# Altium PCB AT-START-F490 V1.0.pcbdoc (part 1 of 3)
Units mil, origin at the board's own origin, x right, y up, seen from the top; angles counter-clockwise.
Board outline 15424.54 x 3536.36 mil, 2 copper layers (Top Layer, Bottom Layer); 130 components, 126 nets, 528 pads, 715 vias.
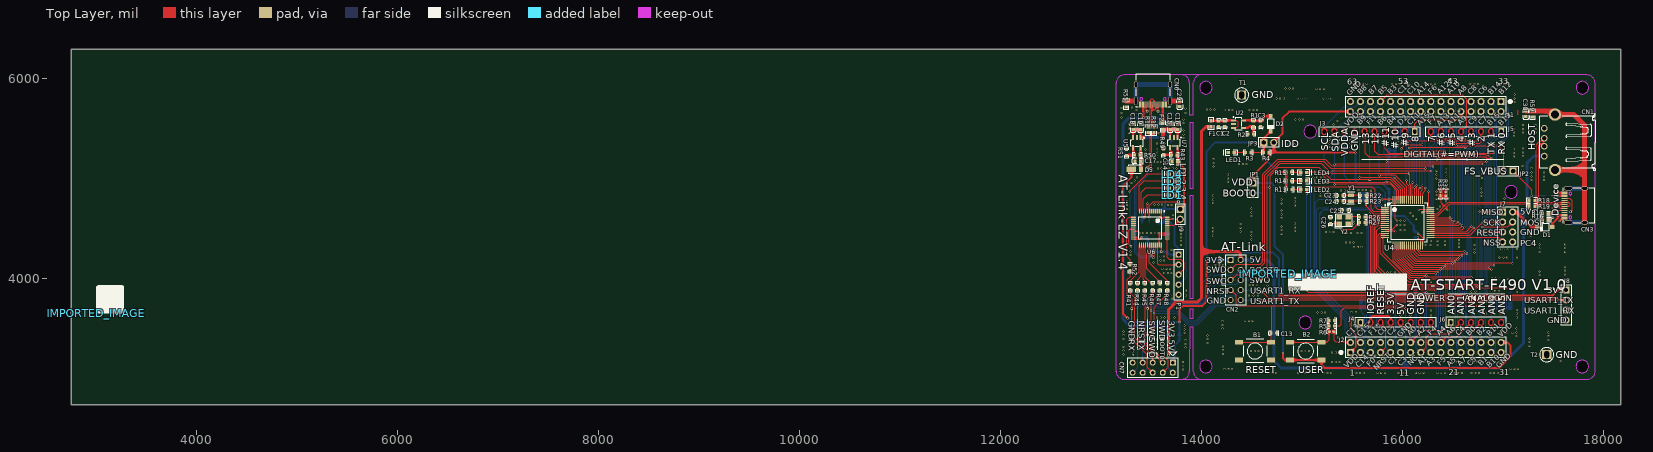
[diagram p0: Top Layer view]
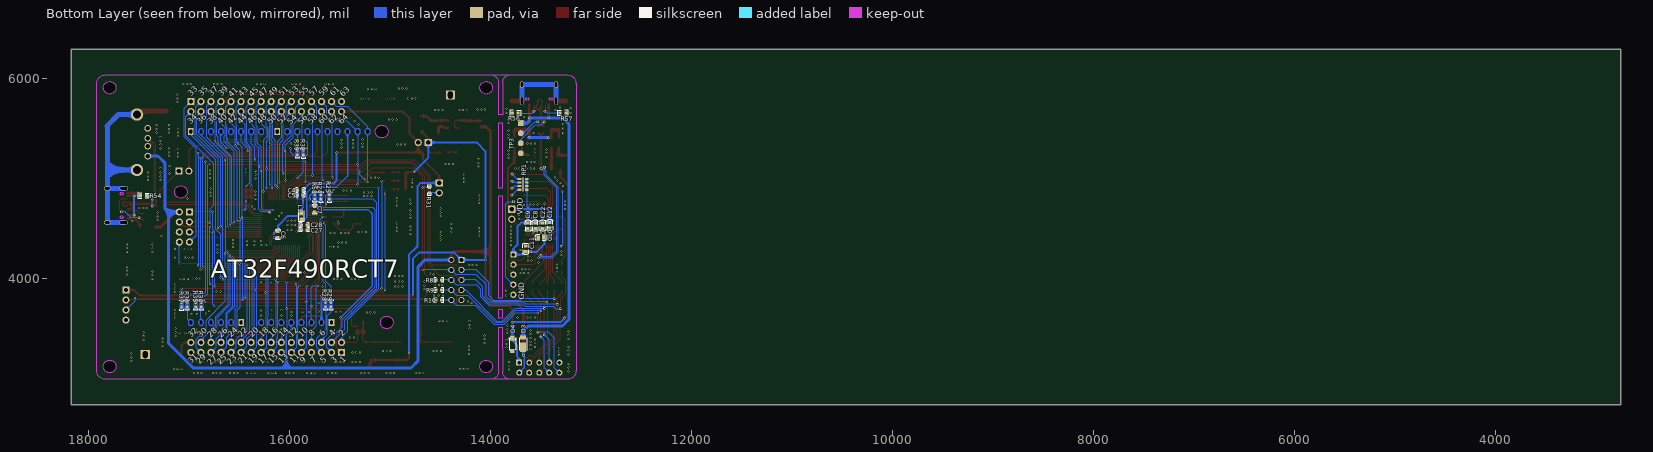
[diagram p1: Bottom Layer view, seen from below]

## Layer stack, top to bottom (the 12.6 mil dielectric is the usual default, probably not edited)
Top Layer: signal copper (thickness not stored)
Dielectric: dielectric 12.6, FR-4, Dk 4.8
Bottom Layer: signal copper (thickness not stored)

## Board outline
18174.54,2750 2750,2750 2750,6286.36 18174.54,6286.36
cut-out: 17855.2,5903.56 ccw(c17792.2,5903.57) 17729.21,5903.57 ccw(c17792.2,5903.57)
cut-out: 17854.57,3128.57 ccw(c17791.57,3128.57) 17728.58,3128.57 ccw(c17791.57,3128.57)
cut-out: 14107.57,3128.57 ccw(c14044.57,3128.57) 13981.58,3128.57 ccw(c14044.57,3128.57)
cut-out: 14107.57,5903.56 ccw(c14044.57,5903.57) 13981.58,5903.57 ccw(c14044.57,5903.57)
cut-out: 17146.57,4866.56 ccw(c17083.57,4866.57) 17020.58,4866.57 ccw(c17083.57,4866.57)
cut-out: 15096.57,3566.57 ccw(c15033.57,3566.57) 14970.58,3566.57 ccw(c15033.57,3566.57)
cut-out: 15146.57,5466.56 ccw(c15083.57,5466.57) 15020.58,5466.57 ccw(c15083.57,5466.57)

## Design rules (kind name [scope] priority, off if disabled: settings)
BoardOutlineClearance Default [All] p0: genericclearance=10 ignorepadtopadclearanceinfootprint=FALSE except(0: Arc-SplitContinuation Track-SplitContinuation SMDPad-SplitContinuation THPad-SplitContinuation Via-SplitContinuation Fill-SplitContinuation Poly-SplitContinuation Region-SplitContinuation Text-SplitContinuation; 6: Track-CutoutEdge SMDPad-CutoutEdge THPad-CutoutEdge Via-CutoutEdge Fill-CutoutEdge Region-CutoutEdge; 11.8: Track-OutlineEdge SMDPad-OutlineEdge THPad-OutlineEdge Via-OutlineEdge Fill-OutlineEdge Region-OutlineEdge Poly-OutlineEdge Text-OutlineEdge)
Clearance Default [(InNet('GND') OR InNet('3V3') OR InNet('ATLK_RX') OR InNet('PA0') OR InNet('VDD') OR InNet('NRST') OR InNet('PC2') OR InNet('PB9') OR InNet('PB3') OR InNet('PA13/SWDIO') OR InNet('PA14/SWCLK') OR InNet('PC5') OR InNet('PC3') OR InNet('PB8') OR InNet('PA10') OR InNet('PA9') OR InNet('PA2') OR InNet('PA3') OR InNet('PA7') OR InNet('PA6') OR InNet('PA5') OR InNet('PF1/HEXT_OUT') OR InNet('PC0') OR InNet('PC1') OR InNet('5V') OR InNet('SWO') OR InNet('LD4') OR InNet('VCC') OR InNet('M-NRST') OR InNet('M-USB_D+') OR InNet('M-USB_D-') OR InNet('USB-') OR InNet('USB+') OR InNet('ATLK_TX') OR InNet('ATLINK_5V') OR InNet('PB10') OR InNet('PB2') OR InNet('PB1') OR InNet('PB0') OR InNet('PC4') OR InNet('PA4') OR InNet('PF5') OR InNet('PF4') OR InNet('PA1') OR InNet('PC6') OR InNet('PB12') OR InNet('PC7') OR InNet('PC8') OR InNet('PC9') OR InNet('PA8') OR InNet('PF6') OR InNet('PF7') OR InNet('PA12') OR InNet('PA11') OR InNet('PA15') OR InNet('PC10') OR InNet('PC11') OR InNet('PC12') OR InNet('PD2') OR InNet('PB4') OR InNet('PB7') OR InNet('PB5') OR InNet('PB6') OR InNet('PF0/HEXT_IN') OR InNet('PC14/LEXT_IN') OR InNet('PC15/LEXT_OUT') OR InNet('PC13') OR InNet('VDDA') OR InNet('PB13') OR InNet('PA11_E') OR InNet('PA12_E') OR InNet('PF0') OR InNet('PC14') OR InNet('PF1') OR InNet('PC15') OR InNet('VCC3.5V') OR InNet('M_ATLK_NRST') OR InNet('M-ATLK_RX') OR InNet('M-ATLK_TX') OR InNet('M_ATLK_BOOT0') OR InNet('LD1') OR InNet('M-SWCLK') OR InNet('LD2') OR InNet('LD3') OR InNet('M_ATLK_SWO') OR InNet('M_ATLK_SWDIO') OR InNet('M_ATLK_SWCLK') OR InNet('M-SWDIO') OR InNet('$1N361') OR InNet('$1N307') OR InNet('$1N334') OR InNet('$1N335') OR InNet('$1N336') OR InNet('$1N337') OR InNet('$1N396') OR InNet('$1N467') OR InNet('$4N239') OR InNet('$4N238') OR InNet('$4N335') OR InNet('$4N333') OR InNet('BOOT0/PF11') OR InNet('$4N462') OR InNet('VBUS_FS') OR InNet('$2N290') OR InNet('$2N326') OR InNet('$2N490') OR InNet('$2N489') OR InNet('$2N337') OR InNet('$2N291') OR InNet('$2N488') OR InNet('$2N360') OR InNet('EGND') OR InNet('FD-') OR InNet('FD+') OR InNet('CC2') OR InNet('CC1') OR InNet('EGND2') OR InNet('FCC2') OR InNet('FCC1') OR InNet('$2N12490') OR InNet('$3N200') OR InNet('$3N199') OR InNet('$3N264') OR InNet('PB15') OR InNet('PB14') OR InNet('PB11'))] p1: gap=7 ignorepadtopadclearanceinfootprint=FALSE except(5: SMDPad-SMDPad SMDPad-THPad THPad-THPad SMDPad-Hole THPad-Hole; 6: Track-Track Track-SMDPad Track-THPad Track-Via SMDPad-Via THPad-Via Via-Via Track-Fill SMDPad-Fill THPad-Fill Via-Fill Fill-Fill Track-Region SMDPad-Region THPad-Region Via-Region Fill-Region Region-Region Track-Poly SMDPad-Poly THPad-Poly Via-Poly Fill-Poly Region-Poly Poly-Poly Track-Text SMDPad-Text THPad-Text Via-Text Fill-Text Region-Text Poly-Text Text-Text Track-Hole Via-Hole Fill-Hole Region-Hole Poly-Hole Text-Hole; 11.8: Track-Sheet SMDPad-Sheet THPad-Sheet Via-Sheet Fill-Sheet Region-Sheet Poly-Sheet Text-Sheet Sheet-Hole)
DiffPairsRouting differentialPair [All] p1: maxuncoupledlength=10 minlimit=6 maxlimit=6 mostfreqgap=6 toplayer_minwidth=6 toplayer_prefwidth=11.1 toplayer_maxwidth=100 bottomlayer_minwidth=6 bottomlayer_prefwidth=11.1 bottomlayer_maxwidth=100
PasteMaskExpansion pasteMaskExpansion [All] p1: expansion=0
PlaneConnect Default [All] p1: planeconnectstyle=Relief reliefexpansion=20 reliefentries=4 reliefconductorwidth=0 reliefairgap=10
PolygonConnect gge24930 [All] p1: connectstyle=Relief reliefentries=4 reliefconductorwidth=10 polygonreliefangle="90 Angle" airgapwidth=10
PolygonConnect gge24930(1) [All] p1: connectstyle=Relief reliefentries=4 reliefconductorwidth=10 polygonreliefangle="90 Angle" airgapwidth=10
RoutingVias Default [All] p1: viastyle="Through Hole" holewidth=12 minholewidth=7.9 maxholewidth=236.2 width=19.7 minwidth=19.7 maxwidth=393.7
SolderMaskExpansion solderMaskExpansion [All] p1: useseparateexpansions=TRUE expansion=2 expansionbottom=2
Width Default [All] p1: maxlimit=1000 minlimit=6 preferedwidth=6

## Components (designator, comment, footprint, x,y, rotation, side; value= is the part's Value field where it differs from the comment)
B1 "BUTTON_SMT,6.0x6.0x4.5mm" BUTTON_SMT_6*6*5 14533.58,3281.57 r0 top
B2 "BUTTON_SMT,6.0x6.0x4.5mm" BUTTON_SMT_6*6*5 15038.58,3281.57 r180 top
C1 "10uF" 0603_C-M 14172.58,5545.37 r90 top
C2 "0.1uF" 0603_C-M 14232.58,5545.37 r90 top
C3 "10uF" 0603_C-M 14590.58,5545.37 r90 top
C4 "4.7uF" 0603_C-M 15896.58,4884.56 r180 bottom
C5 "0.1uF" 0603_C-M 15897.08,4834.56 r180 bottom
C6 "0.1uF" 0603_C-M 16115.6,4442.33 r90 bottom
C7 "0.1uF" 0603_C-M 15750.58,4694.56 r90 bottom
C8 "4.7uF" C0603 13556.58,4528.56 r270 bottom
C9 "CC0603KRX7R9BB104" C0603 13628.58,4528.56 r270 bottom
C10 "CC0603KRX7R9BB104" C0603 13498.58,4412.56 r0 bottom
C11 "CC0603KRX7R9BB104" C0603 13650.58,4300.56 r90 bottom
C12 "CC0603KRX7R9BB104" C0603 13410.58,4534.56 r270 bottom
C13 "0.1uF" 0603_C-M 14720.58,3460.57 r0 top
C14 "CL10A106KP8NNNC" C0603 13736.58,5165.56 r180 top
C15 "CL10A106KP8NNNC" C0603 13689.58,5515.56 r90 top
C16 "CC0603KRX7R9BB104" C0603 13764.58,5515.12 r90 top
C17 "CL10A106KP8NNNC" C0603 13367.58,5173.56 r180 top
C18 "CL10A106KP8NNNC" C0603 13319.58,5514.56 r90 top
C19 "CC0603KRX7R9BB104" C0603 13395.58,5514.12 r90 top
C22 "CC0603KRX7R9BB104" C0603 13480.58,4530.56 r270 bottom
C23 "18pF" 0603_C-M 15383.58,4832.56 r180 top
C24 "18pF" 0603_C-M 15383.58,4773.56 r180 top
C25 "15pF" 0603_C-M 15433.08,4684.56 r180 top
C26 "15pF" 0603_C-M 15283.58,4577.06 r90 top
C27 "1uF" 0603_C-M 15857.08,4488.56 r180 bottom
C28 "0.1uF" 0603_C-M 15857.08,4537.56 r180 bottom
C29 "CC0603KRX7R9BB104" C0603 13784.58,5743.56 r90 top
C30 "CC0603KRX7R9BB104" C0603 17229.58,5643.01 r90 top
CN1 "USB type A" USB-A-TH__USB-AF-90 17466.58,5360.56 r90 top
CN2 "NC(Header 2x5)" HDR2X5#1 14290.92,4189.85 r270 top
CN3 "TYPEC-304-BCP16" USB-C-SMD_TYPEC-304-BCP16#1 17715.58,4731.56 r90 top
CN6 "TYPEC-304-BCP16" USB-C-SMD_TYPEC-304-BCP16#2 13518.58,5835.56 r180 top locked
CN7 "CON1" HDR2X5#2 13715.38,3166.97 r180 top
D1 "DFLS130L-7" SOD-123 17417.58,4515.56 r0 top
D2 "DFLS130L-7" SOD-123 14690.58,5545.36 r90 top
D3 "DFLS130L-7" POWERDI-123_L2.8-W1.8-LS3.7-RD 13676.62,3368.57 r90 bottom
D4 "SMF3.3A" SOD-123_L2.8-W1.8-LS3.7-RD 13782.58,3348.57 r270 bottom
D5 "DFLS130L-7" POWERDI-123_L2.8-W1.8-LS3.7-RD 13350.58,5091.56 r0 top
F1 "SMD0603B050TF" R0603#1 14096.58,5514.86 r90 top
F2 "SMD0603B050TF" R0603#2 13616.58,5518.56 r270 top
IMPORTED_IMAGE "IMPORTED_IMAGE" IMPORTED_IMAGE 3000,3659.57 r0 top
IMPORTED_IMAGE "IMPORTED_IMAGE" IMPORTED_IMAGE 14864.58,4052.57 r0 top
J1 "Header 2x16" HDR-M-2.54_2X16 16233.44,5715.86 r180 top
J2 "Header 2x16" HDR-M-2.54_2X16 16233.88,3318.14 r0 top
J3 "CON10" "FEMALE HEADER 1X10" 16123.87,5466.56 r180 top locked
J4 "CON8" "FEMALE HEADER 1X8" 15583.87,3566.56 r0 top locked
J5 "CON8" "FEMALE HEADER 1X8" 16983.87,5466.56 r180 top locked
J6 "CON6" "FEMALE HEADER 1X6" 16483.87,3566.57 r0 top locked
J7 "Header 4X2" HDR2X4 16998.88,4667.16 r270 top locked
J8 "Header 1x4" HDR1X4 17630.74,3890.57 r270 top locked
J9 "1X2P,Male,DIP_2.54" HDR1X2 13789.38,4693.97 r270 top
JP1 "NC(Header 1x2)" "HEADER 1X2" 14511.58,4956.56 r270 top
JP2 "NC(Header 1x2)" "HEADER 1X2" 17103.58,5073.56 r180 top
JP3 "NC(Header 1x2)" "HEADER 1X2" 14620.58,5358.56 r0 top
L1 "0.5A,600R@100Mhz" 0603_L 15884.58,4623.56 r270 bottom
LD1 "RED" LED0603 13742.58,4833.77 r180 top
LD2 "GREEN" LED0603 13742.58,4903.37 r180 top
LD3 "BLUE" LED0603 13742.58,4972.97 r180 top
LD4 "YELLOW" LED0603 13742.58,5042.56 r180 top
LED1 "RED" LED0603 14328.58,5259.56 r180 top
LED2 "RED" LED0603 14988.58,4890.56 r0 top
LED3 "YELLOW" LED0603 14988.58,4976.56 r0 top
LED4 "GREEN" LED0603 14988.58,5060.56 r0 top
P1 "HDR-M-2.54_1x5" HDR-M-2.54_1X5 13772.58,4042.57 r270 top
R1 "51k" 0603_R-M 14518.58,5545.37 r270 top
R2 "15k" 0603_R-M 14490.58,5444.56 r180 top
R3 "1K" 0603_R-M 14466.58,5259.56 r0 top
R4 "0R" 0603_R-M 14647.58,5258.56 r0 top
R5 "0R" 0603_R-M 15296.58,3530.57 r0 top
R6 "NC" SB-PAD 15296.58,3474.57 r0 top
R7 "100K" 0603_R-M 15296.58,3586.57 r180 top
R8 "470R" 0603_R-M 14518.27,3990.76 r0 bottom
R9 "470R" 0603_R-M 14518.27,3888.76 r0 bottom
R10 "470R" 0603_R-M 14518.27,3790.76 r0 bottom
R11 "0603WAF0000T5E" R0603#2 13469.58,5485.9 r270 top
R12 "0603WAF0000T5E" R0603#2 13528.58,5485.56 r270 top
R13 "1K" 0603_R-M 14872.58,4890.56 r0 top
R14 "1K" 0603_R-M 14871.19,4976.21 r0 top
R15 "1K" 0603_R-M 14871.19,5062.21 r0 top
R16 "0603WAF5101T5E" R0603#2 17423.58,4589.56 r180 top
R17 "0603WAF5101T5E" R0603#2 17422.58,4649.56 r180 top
R18 "0603WAF220JT5E" R0603#2 17291.92,4780.56 r0 top
R19 "0603WAF220JT5E" R0603#2 17291.58,4721.56 r0 top
R22 "0R" 0603_R-M 15609.58,4832.56 r0 top
R23 "0R" 0603_R-M 15611.58,4774.56 r0 top
R24 "NC" SB-PAD 15689.58,4815.56 r270 bottom
R25 "NC" SB-PAD 15605.58,4815.56 r270 bottom
R26 "0R" 0603_R-M 15600.58,4616.56 r0 top
R27 "0R" 0603_R-M 15600.58,4562.56 r0 top
R28 "NC" SB-PAD 15643.58,3742.57 r270 bottom
R29 "NC" SB-PAD 15589.58,3743.57 r270 bottom
R31 "10K" 0603_R-M 14610.58,4883.56 r270 bottom
R32 "NC" SB-PAD 16433.58,4848.44 r270 top
R33 "NC" SB-PAD 16380.58,4848.85 r270 top
R34 "0R" SB-PAD 16880.58,3742.45 r270 bottom
R35 "NC" SB-PAD 16936.58,3741.96 r270 bottom
R36 "NC" SB-PAD 17020.58,3741.45 r270 bottom
R37 "0R" SB-PAD 17076.58,3740.84 r270 bottom
R38 "NC" SB-PAD 15864.58,5253.93 r270 bottom
R39 "0R" SB-PAD 15924.58,5254.56 r270 bottom
R41 "33R" 0603_R-M 13290.58,3920.57 r270 top
R43 "47K" 0603_R-M 13730.42,5236.02 r180 top
R44 "33R" 0603_R-M 13364.58,3920.57 r270 top
R45 "33R" 0603_R-M 13436.58,3920.57 r270 top
R46 "33R" 0603_R-M 13514.58,3922.57 r270 top
R47 "33R" 0603_R-M 13586.58,3924.57 r270 top
R48 "33R" 0603_R-M 13660.58,3920.57 r270 top
R49 "15K" 0603_R-M 13620.58,5264.56 r270 top
R50 "51K" 0603_R-M 13362.58,5233.56 r180 top
R51 "15K" 0603_R-M 13254.58,5258.56 r270 top
R52 "33R" 0603_R-M 13288.58,4110.56 r270 top
R54 "0603WAF1002T5E" R0603#2 17455.92,4827.56 r0 bottom
R55 "RC0603FR-071ML" R0603#2 13250.58,5741.9 r270 top
R56 "0603WAF5101T5E" R0603#2 13755.58,5651.56 r0 bottom
R57 "0603WAF5101T5E" R0603#2 13279.58,5651.56 r180 bottom
R58 "0R" SB-PAD 15750.58,4817.56 r270 bottom
R59 "RC0603FR-071ML" R0603#2 17296.58,5641.9 r270 top
RP1 "1K" 0603*4,8P4R 13640.58,4887.56 r90 bottom
T1 "Testpoint" TESTHOOK 14400.58,5830.56 r270 top
T2 "Testpoint" TESTHOOK 17437.58,3246.57 r90 top
TP3 "1X4P_2.54F" "HDR1X4 - TOP" 13699.93,5551.02 r90 bottom
U2 "RT9080N-08GJ5" SOT-23-5 14382.58,5477.54 r0 top
U4 "AT32F490RxT7" lqfp-64_l10.0-w10.0-p0.50-ls12.0-bl 16053.57,4560.71 r270 top locked
U5 "RT9080N-08GJ5" SOT-23-5 13295.14,5340.91 r270 top
U6 "AT32F403CGT6" "LQFP48 - 2" 13600.09,4673.02 r270 top locked
U7 "RT9080N-08GJ5" SOT-23-5 13664.35,5342.91 r270 top
Y1 "32.768KHz" "XTAL_SOP - FC-12M" 15487.58,4832.56 r270 top
Y2 "CJ13-120001210B20" CRYSTAL-SMD_4P-L3.2-W2.5-BL 15416.58,4583.56 r0 top

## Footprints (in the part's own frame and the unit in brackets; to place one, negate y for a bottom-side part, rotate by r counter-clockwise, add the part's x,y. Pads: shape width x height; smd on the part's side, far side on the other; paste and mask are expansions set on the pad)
0603*4,8P4R [mm]
  rect 0.55x0.95 smd: 1(0,0) 4(2.7,0) 5(2.7,1.85) 8(0,1.85)
  rect 0.5x0.95 smd: 2(0.9,0) 3(1.8,0) 6(1.8,1.85) 7(0.9,1.85)
  silkscreen extent -0.43,0.94 3.1,0.94
0603_C-M [mil]
  rect 30x30 smd: 1(27.5,0) 2(-27.5,0)
  silkscreen extent -50,-21 50,21
0603_L [mm]
  rect 0.93x0.9 smd: 1(-0.77,0) 2(0.77,0)
  silkscreen extent -1.4,-0.64 1.4,0.64
0603_R-M [mil]
  rect 30x30 smd: 1(27.5,0) 2(-27.5,0)
  silkscreen extent -50,-21 50,21
BUTTON_SMT_6*6*5 [mm]
  rect 2x1.2 smd: 1(-4,2.25) 2(4,2.25) 3(-4,-2.25) 4(4,-2.25)
  silkscreen extent -3,-3 3,3
C0603 [mm]
  rect 0.8x0.9 smd: 1(-0.7,0) 2(0.7,0)
  silkscreen extent -1.41,-0.71 1.39,0.72
CRYSTAL-SMD_4P-L3.2-W2.5-BL [mm]
  rect 1.4x1.2 smd: 1(-1.1,-0.85) 2(1.1,-0.85) 3(1.1,0.85) 4(-1.1,0.85)
  silkscreen extent -2.26,-1.91 2.03,1.68
"FEMALE HEADER 1X6" [mm]
  rect 1.4x1.8 hole 0.7 slot 1 at 90 deg: 1(0,0)
  oval 0.6x0.42 hole 0.7 slot 1 at 90 deg: 2(2.54,0) 3(5.08,0) 4(7.62,0) 5(10.16,0) 6(12.7,0)
  Top Layer region: 13.4,-0.2 13.306,-0.55 13.05,-0.806 12.7,-0.9 12.35,-0.806 12.094,-0.55 12,-0.2 12,0.2 12.094,0.55 12.35,0.806 12.7,0.9 13.05,0.806 13.306,0.55 13.4,0.2
  Top Layer region: 10.86,-0.2 10.766,-0.55 10.51,-0.806 10.16,-0.9 9.81,-0.806 9.554,-0.55 9.46,-0.2 9.46,0.2 9.554,0.55 9.81,0.806 10.16,0.9 10.51,0.806 10.766,0.55 10.86,0.2
  Top Layer region: 8.32,-0.2 8.226,-0.55 7.97,-0.806 7.62,-0.9 7.27,-0.806 7.014,-0.55 6.92,-0.2 6.92,0.2 7.014,0.55 7.27,0.806 7.62,0.9 7.97,0.806 8.226,0.55 8.32,0.2
  Top Layer region: 5.78,-0.2 5.686,-0.55 5.43,-0.806 5.08,-0.9 4.73,-0.806 4.474,-0.55 4.38,-0.2 4.38,0.2 4.474,0.55 4.73,0.806 5.08,0.9 5.43,0.806 5.686,0.55 5.78,0.2
  Top Layer region: 3.24,-0.2 3.146,-0.55 2.89,-0.806 2.54,-0.9 2.19,-0.806 1.934,-0.55 1.84,-0.2 1.84,0.2 1.934,0.55 2.19,0.806 2.54,0.9 2.89,0.806 3.146,0.55 3.24,0.2
  Bottom Layer region: 13.4,-0.2 13.306,-0.55 13.05,-0.806 12.7,-0.9 12.35,-0.806 12.094,-0.55 12,-0.2 12,0.2 12.094,0.55 12.35,0.806 12.7,0.9 13.05,0.806 13.306,0.55 13.4,0.2
  Bottom Layer region: 10.86,-0.2 10.766,-0.55 10.51,-0.806 10.16,-0.9 9.81,-0.806 9.554,-0.55 9.46,-0.2 9.46,0.2 9.554,0.55 9.81,0.806 10.16,0.9 10.51,0.806 10.766,0.55 10.86,0.2
  Bottom Layer region: 8.32,-0.2 8.226,-0.55 7.97,-0.806 7.62,-0.9 7.27,-0.806 7.014,-0.55 6.92,-0.2 6.92,0.2 7.014,0.55 7.27,0.806 7.62,0.9 7.97,0.806 8.226,0.55 8.32,0.2
  Bottom Layer region: 5.78,-0.2 5.686,-0.55 5.43,-0.806 5.08,-0.9 4.73,-0.806 4.474,-0.55 4.38,-0.2 4.38,0.2 4.474,0.55 4.73,0.806 5.08,0.9 5.43,0.806 5.686,0.55 5.78,0.2
  Bottom Layer region: 3.24,-0.2 3.146,-0.55 2.89,-0.806 2.54,-0.9 2.19,-0.806 1.934,-0.55 1.84,-0.2 1.84,0.2 1.934,0.55 2.19,0.806 2.54,0.9 2.89,0.806 3.146,0.55 3.24,0.2
  Multi-Layer region: 13.4,-0.2 13.306,-0.55 13.05,-0.806 12.7,-0.9 12.35,-0.806 12.094,-0.55 12,-0.2 12,0.2 12.094,0.55 12.35,0.806 12.7,0.9 13.05,0.806 13.306,0.55 13.4,0.2
  Multi-Layer region: 10.86,-0.2 10.766,-0.55 10.51,-0.806 10.16,-0.9 9.81,-0.806 9.554,-0.55 9.46,-0.2 9.46,0.2 9.554,0.55 9.81,0.806 10.16,0.9 10.51,0.806 10.766,0.55 10.86,0.2
  Multi-Layer region: 8.32,-0.2 8.226,-0.55 7.97,-0.806 7.62,-0.9 7.27,-0.806 7.014,-0.55 6.92,-0.2 6.92,0.2 7.014,0.55 7.27,0.806 7.62,0.9 7.97,0.806 8.226,0.55 8.32,0.2
  Multi-Layer region: 5.78,-0.2 5.686,-0.55 5.43,-0.806 5.08,-0.9 4.73,-0.806 4.474,-0.55 4.38,-0.2 4.38,0.2 4.474,0.55 4.73,0.806 5.08,0.9 5.43,0.806 5.686,0.55 5.78,0.2
  Multi-Layer region: 3.24,-0.2 3.146,-0.55 2.89,-0.806 2.54,-0.9 2.19,-0.806 1.934,-0.55 1.84,-0.2 1.84,0.2 1.934,0.55 2.19,0.806 2.54,0.9 2.89,0.806 3.146,0.55 3.24,0.2
  silkscreen extent -1.27,-1.17 13.97,1.27
"FEMALE HEADER 1X8" [mm]
  rect 1.4x1.8 hole 0.7 slot 1 at 90 deg: 1(0,0)
  oval 0.6x0.42 hole 0.7 slot 1 at 90 deg: 2(2.54,0) 3(5.08,0) 4(7.62,0) 5(10.16,0) 6(12.7,0) 7(15.24,0) 8(17.78,0)
  Top Layer region: 3.24,-0.2 3.146,-0.55 2.89,-0.806 2.54,-0.9 2.19,-0.806 1.934,-0.55 1.84,-0.2 1.84,0.2 1.934,0.55 2.19,0.806 2.54,0.9 2.89,0.806 3.146,0.55 3.24,0.2
  Top Layer region: 5.78,-0.2 5.686,-0.55 5.43,-0.806 5.08,-0.9 4.73,-0.806 4.474,-0.55 4.38,-0.2 4.38,0.2 4.474,0.55 4.73,0.806 5.08,0.9 5.43,0.806 5.686,0.55 5.78,0.2
  Top Layer region: 8.32,-0.2 8.226,-0.55 7.97,-0.806 7.62,-0.9 7.27,-0.806 7.014,-0.55 6.92,-0.2 6.92,0.2 7.014,0.55 7.27,0.806 7.62,0.9 7.97,0.806 8.226,0.55 8.32,0.2
  Top Layer region: 10.86,-0.2 10.766,-0.55 10.51,-0.806 10.16,-0.9 9.81,-0.806 9.554,-0.55 9.46,-0.2 9.46,0.2 9.554,0.55 9.81,0.806 10.16,0.9 10.51,0.806 10.766,0.55 10.86,0.2
  Top Layer region: 13.4,-0.2 13.306,-0.55 13.05,-0.806 12.7,-0.9 12.35,-0.806 12.094,-0.55 12,-0.2 12,0.2 12.094,0.55 12.35,0.806 12.7,0.9 13.05,0.806 13.306,0.55 13.4,0.2
  Top Layer region: 15.94,-0.2 15.846,-0.55 15.59,-0.806 15.24,-0.9 14.89,-0.806 14.634,-0.55 14.54,-0.2 14.54,0.2 14.634,0.55 14.89,0.806 15.24,0.9 15.59,0.806 15.846,0.55 15.94,0.2
  Top Layer region: 18.48,-0.2 18.386,-0.55 18.13,-0.806 17.78,-0.9 17.43,-0.806 17.174,-0.55 17.08,-0.2 17.08,0.2 17.174,0.55 17.43,0.806 17.78,0.9 18.13,0.806 18.386,0.55 18.48,0.2
  Bottom Layer region: 3.24,-0.2 3.146,-0.55 2.89,-0.806 2.54,-0.9 2.19,-0.806 1.934,-0.55 1.84,-0.2 1.84,0.2 1.934,0.55 2.19,0.806 2.54,0.9 2.89,0.806 3.146,0.55 3.24,0.2
  Bottom Layer region: 5.78,-0.2 5.686,-0.55 5.43,-0.806 5.08,-0.9 4.73,-0.806 4.474,-0.55 4.38,-0.2 4.38,0.2 4.474,0.55 4.73,0.806 5.08,0.9 5.43,0.806 5.686,0.55 5.78,0.2
  Bottom Layer region: 8.32,-0.2 8.226,-0.55 7.97,-0.806 7.62,-0.9 7.27,-0.806 7.014,-0.55 6.92,-0.2 6.92,0.2 7.014,0.55 7.27,0.806 7.62,0.9 7.97,0.806 8.226,0.55 8.32,0.2
  Bottom Layer region: 10.86,-0.2 10.766,-0.55 10.51,-0.806 10.16,-0.9 9.81,-0.806 9.554,-0.55 9.46,-0.2 9.46,0.2 9.554,0.55 9.81,0.806 10.16,0.9 10.51,0.806 10.766,0.55 10.86,0.2
  Bottom Layer region: 13.4,-0.2 13.306,-0.55 13.05,-0.806 12.7,-0.9 12.35,-0.806 12.094,-0.55 12,-0.2 12,0.2 12.094,0.55 12.35,0.806 12.7,0.9 13.05,0.806 13.306,0.55 13.4,0.2
  Bottom Layer region: 15.94,-0.2 15.846,-0.55 15.59,-0.806 15.24,-0.9 14.89,-0.806 14.634,-0.55 14.54,-0.2 14.54,0.2 14.634,0.55 14.89,0.806 15.24,0.9 15.59,0.806 15.846,0.55 15.94,0.2
  Bottom Layer region: 18.48,-0.2 18.386,-0.55 18.13,-0.806 17.78,-0.9 17.43,-0.806 17.174,-0.55 17.08,-0.2 17.08,0.2 17.174,0.55 17.43,0.806 17.78,0.9 18.13,0.806 18.386,0.55 18.48,0.2
  Multi-Layer region: 3.24,-0.2 3.146,-0.55 2.89,-0.806 2.54,-0.9 2.19,-0.806 1.934,-0.55 1.84,-0.2 1.84,0.2 1.934,0.55 2.19,0.806 2.54,0.9 2.89,0.806 3.146,0.55 3.24,0.2
  Multi-Layer region: 5.78,-0.2 5.686,-0.55 5.43,-0.806 5.08,-0.9 4.73,-0.806 4.474,-0.55 4.38,-0.2 4.38,0.2 4.474,0.55 4.73,0.806 5.08,0.9 5.43,0.806 5.686,0.55 5.78,0.2
  Multi-Layer region: 8.32,-0.2 8.226,-0.55 7.97,-0.806 7.62,-0.9 7.27,-0.806 7.014,-0.55 6.92,-0.2 6.92,0.2 7.014,0.55 7.27,0.806 7.62,0.9 7.97,0.806 8.226,0.55 8.32,0.2
  Multi-Layer region: 10.86,-0.2 10.766,-0.55 10.51,-0.806 10.16,-0.9 9.81,-0.806 9.554,-0.55 9.46,-0.2 9.46,0.2 9.554,0.55 9.81,0.806 10.16,0.9 10.51,0.806 10.766,0.55 10.86,0.2
  Multi-Layer region: 13.4,-0.2 13.306,-0.55 13.05,-0.806 12.7,-0.9 12.35,-0.806 12.094,-0.55 12,-0.2 12,0.2 12.094,0.55 12.35,0.806 12.7,0.9 13.05,0.806 13.306,0.55 13.4,0.2
  Multi-Layer region: 15.94,-0.2 15.846,-0.55 15.59,-0.806 15.24,-0.9 14.89,-0.806 14.634,-0.55 14.54,-0.2 14.54,0.2 14.634,0.55 14.89,0.806 15.24,0.9 15.59,0.806 15.846,0.55 15.94,0.2
  Multi-Layer region: 18.48,-0.2 18.386,-0.55 18.13,-0.806 17.78,-0.9 17.43,-0.806 17.174,-0.55 17.08,-0.2 17.08,0.2 17.174,0.55 17.43,0.806 17.78,0.9 18.13,0.806 18.386,0.55 18.48,0.2
  silkscreen extent -1.27,-1.17 19.05,1.27
"FEMALE HEADER 1X10" [mm]
  rect 1.4x1.8 hole 0.7 slot 1 at 90 deg: 1(0,0)
  oval 0.6x0.42 hole 0.7 slot 1 at 90 deg: 2(2.54,0) 3(5.08,0) 4(7.62,0) 5(10.16,0) 6(12.7,0) 7(15.24,0) 8(17.78,0) 9(20.32,0) 10(22.86,0)
  Top Layer region: 23.56,-0.2 23.466,-0.55 23.21,-0.806 22.86,-0.9 22.51,-0.806 22.254,-0.55 22.16,-0.2 22.16,0.2 22.254,0.55 22.51,0.806 22.86,0.9 23.21,0.806 23.466,0.55 23.56,0.2
  Top Layer region: 21.02,-0.2 20.926,-0.55 20.67,-0.806 20.32,-0.9 19.97,-0.806 19.714,-0.55 19.62,-0.2 19.62,0.2 19.714,0.55 19.97,0.806 20.32,0.9 20.67,0.806 20.926,0.55 21.02,0.2
  Top Layer region: 18.48,-0.2 18.386,-0.55 18.13,-0.806 17.78,-0.9 17.43,-0.806 17.174,-0.55 17.08,-0.2 17.08,0.2 17.174,0.55 17.43,0.806 17.78,0.9 18.13,0.806 18.386,0.55 18.48,0.2
  Top Layer region: 15.94,-0.2 15.846,-0.55 15.59,-0.806 15.24,-0.9 14.89,-0.806 14.634,-0.55 14.54,-0.2 14.54,0.2 14.634,0.55 14.89,0.806 15.24,0.9 15.59,0.806 15.846,0.55 15.94,0.2
  Top Layer region: 13.4,-0.2 13.306,-0.55 13.05,-0.806 12.7,-0.9 12.35,-0.806 12.094,-0.55 12,-0.2 12,0.2 12.094,0.55 12.35,0.806 12.7,0.9 13.05,0.806 13.306,0.55 13.4,0.2
  Top Layer region: 10.86,-0.2 10.766,-0.55 10.51,-0.806 10.16,-0.9 9.81,-0.806 9.554,-0.55 9.46,-0.2 9.46,0.2 9.554,0.55 9.81,0.806 10.16,0.9 10.51,0.806 10.766,0.55 10.86,0.2
  Top Layer region: 8.32,-0.2 8.226,-0.55 7.97,-0.806 7.62,-0.9 7.27,-0.806 7.014,-0.55 6.92,-0.2 6.92,0.2 7.014,0.55 7.27,0.806 7.62,0.9 7.97,0.806 8.226,0.55 8.32,0.2
  Top Layer region: 5.78,-0.2 5.686,-0.55 5.43,-0.806 5.08,-0.9 4.73,-0.806 4.474,-0.55 4.38,-0.2 4.38,0.2 4.474,0.55 4.73,0.806 5.08,0.9 5.43,0.806 5.686,0.55 5.78,0.2
  Top Layer region: 3.24,-0.2 3.146,-0.55 2.89,-0.806 2.54,-0.9 2.19,-0.806 1.934,-0.55 1.84,-0.2 1.84,0.2 1.934,0.55 2.19,0.806 2.54,0.9 2.89,0.806 3.146,0.55 3.24,0.2
  Bottom Layer region: 23.56,-0.2 23.466,-0.55 23.21,-0.806 22.86,-0.9 22.51,-0.806 22.254,-0.55 22.16,-0.2 22.16,0.2 22.254,0.55 22.51,0.806 22.86,0.9 23.21,0.806 23.466,0.55 23.56,0.2
  Bottom Layer region: 21.02,-0.2 20.926,-0.55 20.67,-0.806 20.32,-0.9 19.97,-0.806 19.714,-0.55 19.62,-0.2 19.62,0.2 19.714,0.55 19.97,0.806 20.32,0.9 20.67,0.806 20.926,0.55 21.02,0.2
  Bottom Layer region: 18.48,-0.2 18.386,-0.55 18.13,-0.806 17.78,-0.9 17.43,-0.806 17.174,-0.55 17.08,-0.2 17.08,0.2 17.174,0.55 17.43,0.806 17.78,0.9 18.13,0.806 18.386,0.55 18.48,0.2
  Bottom Layer region: 15.94,-0.2 15.846,-0.55 15.59,-0.806 15.24,-0.9 14.89,-0.806 14.634,-0.55 14.54,-0.2 14.54,0.2 14.634,0.55 14.89,0.806 15.24,0.9 15.59,0.806 15.846,0.55 15.94,0.2
  Bottom Layer region: 13.4,-0.2 13.306,-0.55 13.05,-0.806 12.7,-0.9 12.35,-0.806 12.094,-0.55 12,-0.2 12,0.2 12.094,0.55 12.35,0.806 12.7,0.9 13.05,0.806 13.306,0.55 13.4,0.2
  Bottom Layer region: 10.86,-0.2 10.766,-0.55 10.51,-0.806 10.16,-0.9 9.81,-0.806 9.554,-0.55 9.46,-0.2 9.46,0.2 9.554,0.55 9.81,0.806 10.16,0.9 10.51,0.806 10.766,0.55 10.86,0.2
  Bottom Layer region: 8.32,-0.2 8.226,-0.55 7.97,-0.806 7.62,-0.9 7.27,-0.806 7.014,-0.55 6.92,-0.2 6.92,0.2 7.014,0.55 7.27,0.806 7.62,0.9 7.97,0.806 8.226,0.55 8.32,0.2
  Bottom Layer region: 5.78,-0.2 5.686,-0.55 5.43,-0.806 5.08,-0.9 4.73,-0.806 4.474,-0.55 4.38,-0.2 4.38,0.2 4.474,0.55 4.73,0.806 5.08,0.9 5.43,0.806 5.686,0.55 5.78,0.2
  Bottom Layer region: 3.24,-0.2 3.146,-0.55 2.89,-0.806 2.54,-0.9 2.19,-0.806 1.934,-0.55 1.84,-0.2 1.84,0.2 1.934,0.55 2.19,0.806 2.54,0.9 2.89,0.806 3.146,0.55 3.24,0.2
  Multi-Layer region: 23.56,-0.2 23.466,-0.55 23.21,-0.806 22.86,-0.9 22.51,-0.806 22.254,-0.55 22.16,-0.2 22.16,0.2 22.254,0.55 22.51,0.806 22.86,0.9 23.21,0.806 23.466,0.55 23.56,0.2
  Multi-Layer region: 21.02,-0.2 20.926,-0.55 20.67,-0.806 20.32,-0.9 19.97,-0.806 19.714,-0.55 19.62,-0.2 19.62,0.2 19.714,0.55 19.97,0.806 20.32,0.9 20.67,0.806 20.926,0.55 21.02,0.2
  Multi-Layer region: 18.48,-0.2 18.386,-0.55 18.13,-0.806 17.78,-0.9 17.43,-0.806 17.174,-0.55 17.08,-0.2 17.08,0.2 17.174,0.55 17.43,0.806 17.78,0.9 18.13,0.806 18.386,0.55 18.48,0.2
  Multi-Layer region: 15.94,-0.2 15.846,-0.55 15.59,-0.806 15.24,-0.9 14.89,-0.806 14.634,-0.55 14.54,-0.2 14.54,0.2 14.634,0.55 14.89,0.806 15.24,0.9 15.59,0.806 15.846,0.55 15.94,0.2
  Multi-Layer region: 13.4,-0.2 13.306,-0.55 13.05,-0.806 12.7,-0.9 12.35,-0.806 12.094,-0.55 12,-0.2 12,0.2 12.094,0.55 12.35,0.806 12.7,0.9 13.05,0.806 13.306,0.55 13.4,0.2
  Multi-Layer region: 10.86,-0.2 10.766,-0.55 10.51,-0.806 10.16,-0.9 9.81,-0.806 9.554,-0.55 9.46,-0.2 9.46,0.2 9.554,0.55 9.81,0.806 10.16,0.9 10.51,0.806 10.766,0.55 10.86,0.2
  Multi-Layer region: 8.32,-0.2 8.226,-0.55 7.97,-0.806 7.62,-0.9 7.27,-0.806 7.014,-0.55 6.92,-0.2 6.92,0.2 7.014,0.55 7.27,0.806 7.62,0.9 7.97,0.806 8.226,0.55 8.32,0.2
  Multi-Layer region: 5.78,-0.2 5.686,-0.55 5.43,-0.806 5.08,-0.9 4.73,-0.806 4.474,-0.55 4.38,-0.2 4.38,0.2 4.474,0.55 4.73,0.806 5.08,0.9 5.43,0.806 5.686,0.55 5.78,0.2
  Multi-Layer region: 3.24,-0.2 3.146,-0.55 2.89,-0.806 2.54,-0.9 2.19,-0.806 1.934,-0.55 1.84,-0.2 1.84,0.2 1.934,0.55 2.19,0.806 2.54,0.9 2.89,0.806 3.146,0.55 3.24,0.2
  silkscreen extent -1.27,-1.17 24.1,1.27
HDR1X2 [mm]
  rect 1.8x1.8 hole 1 slot 1.005 at 0 deg: 1(0,0)
  round 1.8 hole 1 slot 1.005 at 0 deg: 2(2.54,0)
  silkscreen extent -1.27,-1.27 3.81,1.27
HDR1X4 [mm]
  rect 1.8x1.8 hole 1: 1(0,0)
  round 1.8 hole 1: 2(2.54,0) 3(5.08,0) 4(7.62,0)
  silkscreen extent -1.27,-1.27 8.89,1.27
"HDR1X4 - TOP" [mm]
  rect 1.5x1.5 smd: 1(0,0)
  round 1.5 smd: 2(-2.54,0) 3(-5.08,0) 4(-7.62,0)
HDR2X4 [mm]
  rect 1.8x1.8 hole 1: 1(0,0)
  round 1.8 hole 1: 2(0,2.54) 3(2.54,0) 4(2.54,2.54) 5(5.08,0) 6(5.08,2.54) 7(7.62,0) 8(7.62,2.54)
  silkscreen extent -1.27,-1.27 8.89,3.81
HDR2X5#1 [mm]
  rect 1.5x1.5 hole 0.9 slot 0.905 at 0 deg: 1(0,0)
  round 1.5 hole 0.9 slot 0.905 at 0 deg: 2(0,2.54) 3(2.54,0) 4(2.54,2.54) 5(5.08,0) 6(5.08,2.54) 7(7.62,0) 8(7.62,2.54) 9(10.16,0) 10(10.16,2.54)
  silkscreen extent -1.27,-1.27 11.43,3.81
HDR2X5#2 [mm]
  rect 1.5x1.5 hole 0.9: 1(0,0)
  round 1.5 hole 0.9: 2(0,2.54) 3(2.54,0) 4(2.54,2.54) 5(5.08,0) 6(5.08,2.54) 7(7.62,0) 8(7.62,2.54) 9(10.16,0) 10(10.16,2.54)
  silkscreen extent -1.27,-1.27 11.43,3.81
HDR-M-2.54_1X5 [mil]
  rect 62x62 hole 35: 1(-200,0)
  round 62 hole 35: 2(-100,0) 3(0,0) 4(100,0) 5(200,0)
  silkscreen extent -250,-50 250,50
HDR-M-2.54_2X16 [mm]
  rect 1.8x1.8 hole 1: 1(-19.05,-1.27)
  round 1.8 hole 1: 2(-19.05,1.27) 3(-16.51,-1.27) 4(-16.51,1.27) 5(-13.97,-1.27) 6(-13.97,1.27) 7(-11.43,-1.27) 8(-11.43,1.27) 9(-8.89,-1.27) 10(-8.89,1.27) 11(-6.35,-1.27) 12(-6.35,1.27) 13(-3.81,-1.27) 14(-3.81,1.27) 15(-1.27,-1.27) 16(-1.27,1.27) 17(1.27,-1.27) 18(1.27,1.27) 19(3.81,-1.27) 20(3.81,1.27) 21(6.35,-1.27) 22(6.35,1.27) 23(8.89,-1.27) 24(8.89,1.27) 25(11.43,-1.27) 26(11.43,1.27) 27(13.97,-1.27) 28(13.97,1.27) 29(16.51,-1.27) 30(16.51,1.27) 31(19.05,-1.27) 32(19.05,1.27)
  silkscreen extent -20.32,-2.54 20.32,2.54
"HEADER 1X2" [mm]
  rect 1.8x1.8 hole 1 slot 1.005 at 0 deg: 1(0,0)
  round 1.8 hole 1 slot 1.005 at 0 deg: 2(2.54,0)
  silkscreen extent -1.27,-1.27 3.81,1.27
IMPORTED_IMAGE [mil]
  silkscreen extent 0,0 274,276
LED0603 [mil]
  rect 36x32 smd: 1(-0.04,0.2) 2(60.96,0.2)
  silkscreen extent -28,-28 110,27
"LQFP48 - 2" [mm]
  rect 1.2x0.3 smd: 1(0,0) 2(0,-0.5) 3(0,-1) 4(0,-1.5) 5(0,-2) 6(0,-2.5) 7(0,-3) 8(0,-3.5) 9(0,-4) 10(0,-4.5) 11(0,-5) 12(0,-5.5) 25(8.5,-5.5) 26(8.5,-5) 27(8.5,-4.5) 28(8.5,-4) 29(8.5,-3.5) 30(8.5,-3) 31(8.5,-2.5) 32(8.5,-2) 33(8.5,-1.5) 34(8.5,-1) 35(8.5,-0.5) 36(8.5,0)
  rect 0.3x1.2 smd: 13(1.5,-7) 14(2,-7) 15(2.5,-7) 16(3,-7) 17(3.5,-7) 18(4,-7) 19(4.5,-7) 20(5,-7) 21(5.5,-7) 22(6,-7) 23(6.5,-7) 24(7,-7) 37(7,1.5) 38(6.5,1.5) 39(6,1.5) 40(5.5,1.5) 41(5,1.5) 42(4.5,1.5) 43(4,1.5) 44(3.5,1.5) 45(3,1.5) 46(2.5,1.5) 47(2,1.5) 48(1.5,1.5)
  silkscreen extent -0.12,-5.71 7.11,0.89
lqfp-64_l10.0-w10.0-p0.50-ls12.0-bl [mm]
  oval 0.268x2 smd: 1(-3.75,-5.75) 2(-3.25,-5.75) 3(-2.75,-5.75) 4(-2.25,-5.75) 5(-1.75,-5.75) 6(-1.25,-5.75) 7(-0.75,-5.75) 8(-0.25,-5.75) 9(0.25,-5.75) 10(0.75,-5.75) 11(1.25,-5.75) 12(1.75,-5.75) 13(2.25,-5.75) 14(2.75,-5.75) 15(3.25,-5.75) 16(3.75,-5.75) 33(3.75,5.75) 34(3.25,5.75) 35(2.75,5.75) 36(2.25,5.75) 37(1.75,5.75) 38(1.25,5.75) 39(0.75,5.75) 40(0.25,5.75) 41(-0.25,5.75) 42(-0.75,5.75) 43(-1.25,5.75) 44(-1.75,5.75) 45(-2.25,5.75) 46(-2.75,5.75) 47(-3.25,5.75) 48(-3.75,5.75)
  oval 2x0.268 smd: 17(5.75,-3.75) 18(5.75,-3.25) 19(5.75,-2.75) 20(5.75,-2.25) 21(5.75,-1.75) 22(5.75,-1.25) 23(5.75,-0.75) 24(5.75,-0.25) 25(5.75,0.25) 26(5.75,0.75) 27(5.75,1.25) 28(5.75,1.75) 29(5.75,2.25) 30(5.75,2.75) 31(5.75,3.25) 32(5.75,3.75) 49(-5.75,3.75) 50(-5.75,3.25) 51(-5.75,2.75) 52(-5.75,2.25) 53(-5.75,1.75) 54(-5.75,1.25) 55(-5.75,0.75) 56(-5.75,0.25) 57(-5.75,-0.25) 58(-5.75,-0.75) 59(-5.75,-1.25) 60(-5.75,-1.75) 61(-5.75,-2.25) 62(-5.75,-2.75) 63(-5.75,-3.25) 64(-5.75,-3.75)
  silkscreen extent -5,-5.79 5,5
POWERDI-123_L2.8-W1.8-LS3.7-RD [mm]
  rect 2.4x1.5 smd: 1(-1.187,0)
  rect 1.05x1.5 smd: 2(1.187,0)
  silkscreen extent -2,-1 1.2,1
R0603#1 [mil]
  rect 36x32 smd: 1(-0.04,0.2) 2(60.96,0.2)
  silkscreen extent -28,-27 89,27
R0603#2 [mil]
  rect 31.75x34.02 smd: 1(-29.66,0) 2(29.66,0)
  silkscreen extent -55,-26 55,26
SB-PAD [mm]
  oval 0.735x0.6 smd: 1(-0.587,0)
  oval 0.791x0.6 smd: 2(0.541,0)
  Top Layer region: -1.2,-0.5 -1.2,0.5 -0.418,0.5 0.025,0 -0.433,-0.5
  Top Layer region: -0.119,0.5 0.381,0 -0.119,-0.5 1.2,-0.5 1.2,0.5
  silkscreen extent -1.28,-0.58 1.28,0.58
SOD-123 [mm]
  rect 1.2x1 smd: 1(1.905,0) 2(-1.905,0)
  silkscreen extent -1.14,-0.89 1.14,0.89
SOD-123_L2.8-W1.8-LS3.7-RD [mm]
  rect 0.95x1.15 smd: 1(-1.692,0) 2(1.692,0)
  silkscreen extent -1.63,-0.94 1.41,0.94
SOT-23-5 [mil]
  rect 50x20 smd: 1(-65,100) 2(-65,63) 3(-65,25) 4(35,25) 5(35,100)
  silkscreen extent -65,1 18,135
TESTHOOK [mm]
  rect 2.3x2.3 hole 1.2 slot 1.8 at 0 deg: 1(0,0)
  silkscreen extent -1.8,-1.8 1.8,1.8
USB-A-TH__USB-AF-90 [mm]
  round 1.7 hole 1.1 copper offset 0,0: 1(-3.5,1.355) 4(3.5,1.355)
  round 1.7 hole 1.1: 2(-1,1.355) 3(1,1.355)
  round 3.1 hole 2.1: SH1(7,-1.355) SH2(-7,-1.355)
  silkscreen extent -7.22,-11.51 7.22,2.49
USB-C-SMD_TYPEC-304-BCP16#1 [mil]
  oval 39.4x82.7 hole 23.6 slot 70.9 at 90 deg: 13(-170.1,64.3) 14(170.1,64.3)
  oval 39.4x63 hole 23.6 slot 47.2 at 90 deg: 15(-170.1,-100.3) 16(170.1,-100.3)
  rect 23.6x57.1 smd: A1B12(-127,100.3) A4B9(-96.5,100.3) B1A12(126.8,100.3) B4A9(96.5,100.3)
  rect 11.8x57.1 smd: A5(-49.2,100.3) A6(-9.8,100.3) A7(9.8,100.3) A8(49.2,100.3) B5(68.9,100.3) B6(29.5,100.3) B7(-29.5,100.3) B8(-68.9,100.3)
  Board Outline Layer circle w0.2: c117.3,43.4 r13.8
  Board Outline Layer circle w0.2: c-117.3,43.4 r13.8
  Board Outline Layer circle w10: c117.3,43.4 r13.8
  Board Outline Layer circle w10: c-117.3,43.4 r13.8
  Multi-Layer board cut-out: 117.3,29.6 123.29,30.97 128.09,34.79 130.76,40.33 130.76,46.47 128.1,52.01 123.29,55.84 117.31,57.2 117.31,57.21 111.32,55.84 106.51,52.01 103.85,46.48 103.85,40.33 106.51,34.8 111.31,30.97 117.3,29.6
  Multi-Layer board cut-out: -117.3,29.6 -111.31,30.97 -106.51,34.79 -103.84,40.33 -103.84,46.47 -106.5,52.01 -111.31,55.84 -117.29,57.2 -117.29,57.21 -123.28,55.84 -128.09,52.01 -130.75,46.48 -130.75,40.33 -128.09,34.8 -123.29,30.97 -117.3,29.6
  silkscreen extent -170,-200 170,120
USB-C-SMD_TYPEC-304-BCP16#2 [mil]
  oval 39.4x82.7 hole 23.6 slot 70.9 at 90 deg: 13(-170.1,64.3) 14(170.1,64.3)
  oval 39.4x63 hole 23.6 slot 47.2 at 90 deg: 15(-170.1,-100.3) 16(170.1,-100.3)
  rect 23.6x57.1 smd: A1B12(-127,100.3) A4B9(-96.5,100.3) B1A12(126.8,100.3) B4A9(96.5,100.3)
  rect 11.8x57.1 smd: A5(-49.2,100.3) A6(-9.8,100.3) A7(9.8,100.3) A8(49.2,100.3) B5(68.9,100.3) B6(29.5,100.3) B7(-29.5,100.3) B8(-68.9,100.3)
  Board Outline Layer circle w0.2: c117.3,43.4 r13.8
  Board Outline Layer circle w0.2: c-117.3,43.4 r13.8
  Board Outline Layer circle w10: c117.3,43.4 r13.8
  Board Outline Layer circle w10: c-117.3,43.4 r13.8
  Multi-Layer board cut-out: 103.5,43.4 104.87,37.41 108.69,32.61 114.23,29.94 120.37,29.94 125.91,32.6 129.74,37.41 131.1,43.39 131.11,43.39 129.74,49.38 125.91,54.19 120.38,56.85 114.23,56.85 108.7,54.19 104.87,49.39 103.5,43.4
  Multi-Layer board cut-out: -131.1,43.4 -129.73,37.41 -125.91,32.61 -120.37,29.94 -114.23,29.94 -108.69,32.6 -104.86,37.41 -103.5,43.39 -103.49,43.39 -104.86,49.38 -108.69,54.19 -114.22,56.85 -120.37,56.85 -125.9,54.19 -129.73,49.39 -131.1,43.4
  silkscreen extent -170,-200 170,120
"XTAL_SOP - FC-12M" [mm]
  rect 0.8x1.5 smd: 1(0,0) 2(1.5,0)
  silkscreen extent -0.81,-0.99 2.29,0.94

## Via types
v1: diameter 19.68, hole 11.81, Top Layer to Bottom Layer, 622 vias
v2: diameter 19.69, hole 11.81, Top Layer to Bottom Layer, 42 vias
v3: diameter 23.62, hole 11.81, Top Layer to Bottom Layer, 17 vias
v4: diameter 27.56, hole 13.78, Top Layer to Bottom Layer, 15 vias
v5: diameter 19.7, hole 11.81, Top Layer to Bottom Layer, 10 vias
v6: diameter 24, hole 12, Top Layer to Bottom Layer, 7 vias
v7: diameter 27.56, hole 15.75, Top Layer to Bottom Layer, 2 vias

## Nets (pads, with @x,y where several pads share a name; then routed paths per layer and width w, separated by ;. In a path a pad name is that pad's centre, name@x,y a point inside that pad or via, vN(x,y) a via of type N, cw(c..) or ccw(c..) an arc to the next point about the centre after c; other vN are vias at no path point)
3V3: CN2.1 CN7.1 D2.2 D4.1 D5.1 J4.2 J4.4 J8.1 JP3.1 R3.1 R4.2 R13.2 R14.2 R15.2 | length 10599.7
  Top Layer w10: R3.1@14494.08,5259.56 14495.08,5258.56 R4.2@14620.08,5258.56
  Top Layer w15: v2(14764.58,5062.56) 14764.92,5062.22 R15.2@14843.69,5062.21
  Top Layer w20: v7(13264.34,3610.01) 13221.01,3653.34 13221.01,4929.24 13303.83,5012.05 D5.1@13303.83,5091.56 ; v2(13782.58,3570.57) 13782.58,3694.57 13820.58,3732.57 14008.58,3732.57 14051.58,3775.57 v2(14051.58,4190.56) ; R4.2@14620.08,5258.56 14620.58,5259.06 JP3.1@14620.58,5358.56 14620.58,5400.36 D2.2@14690.58,5470.36 ; v1(14773.58,3837.57) 14773.86,3837.28 v1(15683.86,3837.28) 17499.28,3837.28 17552.58,3890.57 J8.1@17630.74,3890.57 ; R15.2@14843.69,5062.21 14845.08,5060.84 R13.2@14845.08,4890.56 ; J4.2@15683.86,3566.56 15683.88,3611.86 15702.58,3630.57 15863.58,3630.57 15883.88,3610.26 J4.4@15883.86,3566.56
  Bottom Layer w15: JP3.1@14620.58,5358.56 14620.58,5206.56 v2(14764.58,5062.56) ; v1@15683.58,3837.57 v1(15683.86,3837.28)
  Bottom Layer w20: v7(13264.34,3610.01) 13303.8,3570.57 v2(13782.58,3570.57) D4.1@13782.58,3415.2 13782.58,3388.68 13737.92,3344.01 13737.92,3230.01 13715.34,3207.45 CN7.1@13715.34,3167.01 ; JP3.1@14620.58,5358.56 14138.58,5358.56 14051.58,5271.56 v2(14051.58,4190.56) 14290.2,4190.56 CN2.1@14290.92,4189.85 14365.65,4264.56 14708.58,4264.56 14773.58,4199.56 v1(14773.58,3837.57) ; J4.2@15683.86,3566.56 v1(15683.86,3837.28)
5V: CN1.1 CN2.2 CN7.2 D1.2 D3.1 F1.1 J4.5 J7.2 | length 10223.9
  Top Layer w30: v7(13672.58,3240.57) 13672.58,3694.57 13750.58,3772.57 13962.58,3772.57 14000.58,3810.57 14000.58,5470.56 14044.89,5514.88 F1.1@14096.38,5514.88 ; 14000.58,4238.98 14003.3,4238.98 14036.13,4271.81 ; 14000.58,4305.48 14002.46,4305.48 14036.13,4271.81 ; CN2.2@14390.92,4189.85 14390.92,4250.22 14369.33,4271.81 14036.13,4271.81 ; J7.2@17098.88,4667.16 17133.97,4667.16 17285.58,4515.56 D1.2@17342.58,4515.56
  Bottom Layer w15: D3.1@13676.62,3321.82 13676.58,3240.57 13664.58,3228.57 13664.58,3117.78 CN7.2@13715.34,3067.01 ; J4.5@15982.88,3566.56 15982.88,3499.26 16034.07,3448.07 16033.55,3116.86 16031.05,3114.36 ; 16032.05,3110.43 16032.05,3114.36
  Bottom Layer w30: CN2.2@14390.92,4189.85 14653.3,4189.85 14720.58,4122.56 14720.58,3185.66 14791.89,3114.36 16031.05,3114.36 16032.05,3114.36 16960.38,3114.36 17205.58,3359.57 17205.58,4608.84 ; J7.2@17098.88,4667.16 17204.25,4667.16 ; 17204.25,4610.16 17205.58,4608.84 ; 17204.25,4664.16 17205.58,4665.49 ; 17205.58,4665.84 17205.58,4665.49 ; 17239.58,4698.49 17239.58,4699.49 ; 17310.77,5222.76 CN1.1@17413.23,5222.77 ; 17310.77,5223.76 17239.58,5152.56 17239.58,4699.49 ; 17205.58,4608.84 17205.58,4665.49 ; 17205.58,4665.49 17239.58,4699.49
$1N307: J9.2 U6.44 | length 154.6
  Top Layer w6: U6.44@13659.15,4535.23 13730.56,4535.23 J9.2@13789.34,4594.02
$1N334: LD4.1 RP1.5 | length 138.2
  Top Layer w6: LD4.1@13742.62,5042.36 13785.37,5042.36 v4(13786.58,5043.56)
  Bottom Layer w6: RP1.5@13713.41,4993.86 13736.88,4993.86 v4(13786.58,5043.56)
$1N335: LD3.1 RP1.6 | length 123.1
  Top Layer w6: LD3.1@13742.62,4972.76 13785.38,4972.76 v4(13786.58,4971.56)
  Bottom Layer w6: RP1.6@13713.41,4958.44 13773.44,4958.44 v4(13786.58,4971.56)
